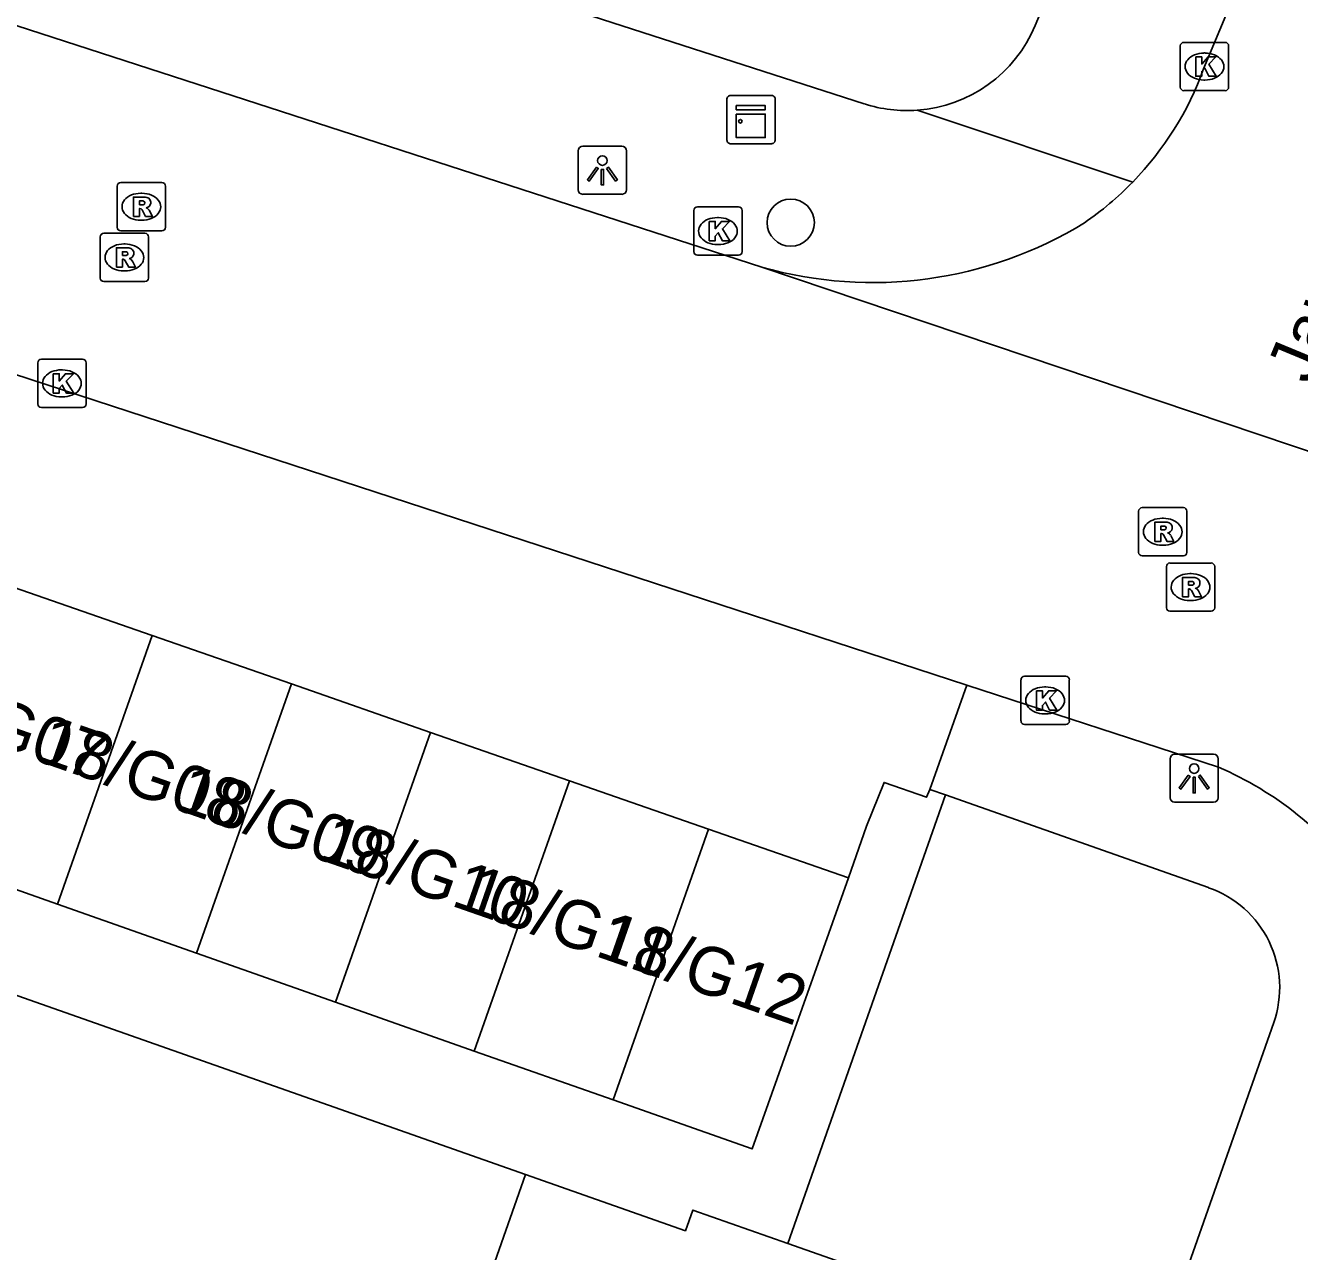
# Model space of a CAD drawing. Extents: x 163268 to 164360, y 381529 to 382285.
# Drawn here: x 163881.64 to 163908.02, y 381955.99 to 381981.39 of the extents above; entities that cross this region are included whole.
import ezdxf

# ---------------------------------------------------------------- set-up
doc = ezdxf.new("R2010")
doc.units = 0
for name, color, linetype in [('IMGEO_Boom', 7, 'Continuous'), ('IMGEO_Kast', 7, 'Continuous'), ('IMGEO_Kolk', 7, 'Continuous'), ('IMGEO_Lichtpunt', 7, 'Continuous'), ('IMGEO_Openbare_ruimte_label', 7, 'Continuous'), ('IMGEO_Pand', 7, 'Continuous'), ('IMGEO_Pand_nummerreeks', 7, 'Continuous'), ('IMGEO_Rijbaan_lokaal_open', 7, 'Continuous'), ('IMGEO_Rioolput', 7, 'Continuous'), ('IMGEO_Voetpad_open', 7, 'Continuous')]:
    doc.layers.add(name, color=color, linetype=linetype)

msp = doc.modelspace()

# ---------------------------------------------------------------- linework, layer by layer
at = {"layer": 'IMGEO_Boom'}
msp.add_circle((163897.485, 381977.305), 0.489, dxfattribs=at)
at = {"layer": 'IMGEO_Kast'}
for p, q in [((163896.163, 381979.014), (163896.163, 381979.855)), ((163896.163, 381979.855), (163896.163, 381979.014)), ((163896.238, 381979.939), (163897.079, 381979.939)), ((163897.079, 381979.939), (163896.238, 381979.939)), ((163897.163, 381979.864), (163897.163, 381979.023)), ((163897.163, 381979.023), (163897.163, 381979.864)), ((163897.088, 381978.939), (163896.247, 381978.939)), ((163896.247, 381978.939), (163897.088, 381978.939))]:
    msp.add_line(p, q, dxfattribs=at)
for points in [[(163896.358, 381979.729), (163896.958, 381979.729), (163896.958, 381979.644), (163896.358, 381979.644), (163896.358, 381979.729)], [(163896.358, 381979.554), (163896.958, 381979.554), (163896.958, 381979.065), (163896.358, 381979.065), (163896.358, 381979.554)]]:
    msp.add_lwpolyline(points, dxfattribs=at)
msp.add_circle((163896.442, 381979.403), 0.0377, dxfattribs=at)
for centre, start, end in [((163896.241, 381979.861), 92.4484, 184.2845), ((163896.241, 381979.861), 92.4484, 184.2845), ((163897.085, 381979.861), 2.4484, 94.2845), ((163897.085, 381979.861), 2.4484, 94.2845), ((163896.241, 381979.017), 182.4484, 274.2845), ((163896.241, 381979.017), 182.4484, 274.2845), ((163897.085, 381979.017), 272.4484, 4.2845), ((163897.085, 381979.017), 272.4484, 4.2845)]:
    msp.add_arc(centre, 0.0779, start, end, dxfattribs=at)
at = {"layer": 'IMGEO_Kolk'}
for p, q in [((163905.552, 381980.112), (163905.552, 381980.964)), ((163905.627, 381981.038), (163906.479, 381981.038)), ((163906.04, 381980.818), (163906.065, 381980.818)), ((163906.553, 381980.964), (163906.553, 381980.112)), ((163906.479, 381980.038), (163905.627, 381980.038)), ((163906.063, 381980.258), (163906.038, 381980.258)), ((163895.477, 381976.704), (163895.477, 381977.556)), ((163895.552, 381977.63), (163896.404, 381977.63)), ((163895.965, 381977.41), (163895.99, 381977.41)), ((163896.478, 381977.556), (163896.478, 381976.704)), ((163895.988, 381976.85), (163895.963, 381976.85)), ((163896.404, 381976.63), (163895.552, 381976.63)), ((163881.967, 381974.475), (163882.819, 381974.475)), ((163881.892, 381973.549), (163881.892, 381974.401)), ((163882.38, 381974.255), (163882.405, 381974.255)), ((163882.893, 381974.401), (163882.893, 381973.549)), ((163882.403, 381973.695), (163882.378, 381973.695)), ((163882.819, 381973.475), (163881.967, 381973.475)), ((163902.328, 381967.909), (163903.18, 381967.909)), ((163902.253, 381966.983), (163902.253, 381967.835)), ((163902.741, 381967.689), (163902.766, 381967.689)), ((163903.254, 381967.835), (163903.254, 381966.983)), ((163902.764, 381967.129), (163902.739, 381967.129)), ((163903.18, 381966.909), (163902.328, 381966.909))]:
    msp.add_line(p, q, dxfattribs=at)
for points in [[(163905.552, 381980.112), (163905.552, 381980.964)], [(163905.627, 381981.038), (163906.479, 381981.038)], [(163906.553, 381980.964), (163906.553, 381980.112)], [(163905.873, 381980.738), (163905.996, 381980.738), (163905.996, 381980.587), (163906.126, 381980.738), (163906.29, 381980.738), (163906.144, 381980.587), (163906.297, 381980.338), (163906.145, 381980.338), (163906.06, 381980.502), (163905.996, 381980.435), (163905.996, 381980.338), (163905.873, 381980.338), (163905.873, 381980.738)], [(163906.479, 381980.038), (163905.627, 381980.038)], [(163895.477, 381976.704), (163895.477, 381977.556)], [(163895.552, 381977.63), (163896.404, 381977.63)], [(163896.478, 381977.556), (163896.478, 381976.704)], [(163895.798, 381977.33), (163895.921, 381977.33), (163895.921, 381977.179), (163896.051, 381977.33), (163896.215, 381977.33), (163896.069, 381977.179), (163896.222, 381976.93), (163896.07, 381976.93), (163895.985, 381977.094), (163895.921, 381977.027), (163895.921, 381976.93), (163895.798, 381976.93), (163895.798, 381977.33)], [(163896.404, 381976.63), (163895.552, 381976.63)], [(163881.967, 381974.475), (163882.819, 381974.475)], [(163881.892, 381973.549), (163881.892, 381974.401)], [(163882.893, 381974.401), (163882.893, 381973.549)], [(163882.213, 381974.175), (163882.336, 381974.175), (163882.336, 381974.024), (163882.466, 381974.175), (163882.63, 381974.175), (163882.484, 381974.024), (163882.637, 381973.775), (163882.485, 381973.775), (163882.4, 381973.939), (163882.336, 381973.872), (163882.336, 381973.775), (163882.213, 381973.775), (163882.213, 381974.175)], [(163882.819, 381973.475), (163881.967, 381973.475)], [(163902.328, 381967.909), (163903.18, 381967.909)], [(163902.253, 381966.983), (163902.253, 381967.835)], [(163902.574, 381967.609), (163902.697, 381967.609), (163902.697, 381967.458), (163902.827, 381967.609), (163902.991, 381967.609), (163902.845, 381967.458), (163902.998, 381967.209), (163902.846, 381967.209), (163902.761, 381967.373), (163902.697, 381967.306), (163902.697, 381967.209), (163902.574, 381967.209), (163902.574, 381967.609)], [(163903.254, 381967.835), (163903.254, 381966.983)], [(163903.18, 381966.909), (163902.328, 381966.909)]]:
    msp.add_lwpolyline(points, dxfattribs=at)
for centre, start, end in [((163905.629, 381980.962), 91.552, 178.448), ((163905.629, 381980.962), 91.552, 178.448), ((163906.477, 381980.962), 1.552, 88.448), ((163906.477, 381980.962), 1.552, 88.448), ((163905.629, 381980.114), 181.552, 268.448), ((163905.629, 381980.114), 181.552, 268.448), ((163906.477, 381980.114), 271.552, 358.448), ((163906.477, 381980.114), 271.552, 358.448), ((163895.554, 381977.554), 91.552, 178.448), ((163895.554, 381977.554), 91.552, 178.448), ((163896.402, 381977.554), 1.552, 88.448), ((163896.402, 381977.554), 1.552, 88.448), ((163895.554, 381976.706), 181.552, 268.448), ((163895.554, 381976.706), 181.552, 268.448), ((163896.402, 381976.706), 271.552, 358.448), ((163896.402, 381976.706), 271.552, 358.448), ((163881.969, 381974.399), 91.552, 178.448), ((163881.969, 381974.399), 91.552, 178.448), ((163882.817, 381974.399), 1.552, 88.448), ((163882.817, 381974.399), 1.552, 88.448), ((163881.969, 381973.551), 181.552, 268.448), ((163881.969, 381973.551), 181.552, 268.448), ((163882.817, 381973.551), 271.552, 358.448), ((163882.817, 381973.551), 271.552, 358.448), ((163902.33, 381967.833), 91.552, 178.448), ((163902.33, 381967.833), 91.552, 178.448), ((163903.178, 381967.833), 1.552, 88.448), ((163903.178, 381967.833), 1.552, 88.448), ((163902.33, 381966.985), 181.552, 268.448), ((163902.33, 381966.985), 181.552, 268.448), ((163903.178, 381966.985), 271.552, 358.448), ((163903.178, 381966.985), 271.552, 358.448)]:
    msp.add_arc(centre, 0.0765, start, end, dxfattribs=at)
for centre, major_axis, ratio, start_param, end_param in [((163906.039, 381980.538), (-0.387, 0.002), 0.722429, 4.712389, 7.853982), ((163906.064, 381980.538), (-0.39, 0.002), 0.717154, 1.570796, 4.712389), ((163895.964, 381977.13), (-0.387, 0.002), 0.722429, 4.712389, 7.853982), ((163895.989, 381977.13), (-0.39, 0.002), 0.717154, 1.570796, 4.712389), ((163882.379, 381973.975), (-0.387, 0.002), 0.722429, 4.712389, 7.853982), ((163882.404, 381973.975), (-0.39, 0.002), 0.717154, 1.570796, 4.712389), ((163902.74, 381967.409), (-0.387, 0.002), 0.722429, 4.712389, 7.853982), ((163902.765, 381967.409), (-0.39, 0.002), 0.717154, 1.570796, 4.712389)]:
    msp.add_ellipse(centre, major_axis=major_axis, ratio=ratio, start_param=start_param, end_param=end_param, dxfattribs=at)
at = {"layer": 'IMGEO_Lichtpunt'}
for p, q in [((163893.086, 381978.792), (163893.086, 381977.985)), ((163893.086, 381978.792), (163893.086, 381977.985)), ((163893.988, 381978.887), (163893.18, 381978.887)), ((163893.988, 381978.887), (163893.18, 381978.887)), ((163894.082, 381977.985), (163894.082, 381978.792)), ((163894.082, 381977.985), (163894.082, 381978.792)), ((163893.18, 381977.891), (163893.988, 381977.891)), ((163893.18, 381977.891), (163893.988, 381977.891)), ((163906.242, 381966.295), (163905.434, 381966.295)), ((163906.242, 381966.295), (163905.434, 381966.295)), ((163905.34, 381966.2), (163905.34, 381965.393)), ((163905.34, 381966.2), (163905.34, 381965.393)), ((163906.336, 381965.393), (163906.336, 381966.2)), ((163906.336, 381965.393), (163906.336, 381966.2)), ((163905.434, 381965.299), (163906.242, 381965.299)), ((163905.434, 381965.299), (163906.242, 381965.299))]:
    msp.add_line(p, q, dxfattribs=at)
for points in [[(163893.46, 381978.456), (163893.499, 381978.428), (163893.311, 381978.166), (163893.273, 381978.193), (163893.46, 381978.456)], [(163893.672, 381978.428), (163893.71, 381978.455), (163893.897, 381978.193), (163893.858, 381978.165), (163893.672, 381978.428)], [(163893.562, 381978.408), (163893.609, 381978.408), (163893.609, 381978.086), (163893.562, 381978.086), (163893.562, 381978.408)], [(163905.714, 381965.864), (163905.753, 381965.836), (163905.565, 381965.574), (163905.527, 381965.601), (163905.714, 381965.864)], [(163905.816, 381965.816), (163905.863, 381965.816), (163905.863, 381965.494), (163905.816, 381965.494), (163905.816, 381965.816)], [(163905.926, 381965.836), (163905.964, 381965.863), (163906.151, 381965.601), (163906.112, 381965.573), (163905.926, 381965.836)]]:
    msp.add_lwpolyline(points, dxfattribs=at)
for centre in [(163893.585, 381978.59), (163905.839, 381965.998)]:
    msp.add_circle(centre, 0.0994, dxfattribs=at)
for centre, start, end in [((163893.18, 381978.792), 90, 180), ((163893.18, 381978.792), 90, 180), ((163893.988, 381978.792), 0, 90), ((163893.988, 381978.792), 0, 90), ((163893.18, 381977.985), 180, 270), ((163893.18, 381977.985), 180, 270), ((163893.988, 381977.985), 270, 0), ((163893.988, 381977.985), 270, 360), ((163905.434, 381966.2), 90, 180), ((163905.434, 381966.2), 90, 180), ((163906.242, 381966.2), 0, 90), ((163906.242, 381966.2), 0, 90), ((163905.434, 381965.393), 180, 270), ((163905.434, 381965.393), 180, 270), ((163906.242, 381965.393), 270, 0), ((163906.242, 381965.393), 270, 360)]:
    msp.add_arc(centre, 0.0946, start, end, dxfattribs=at)
at = {"layer": 'IMGEO_Pand'}
for points in [[(163881.384, 381969.754), (163884.264, 381968.751)], [(163884.264, 381968.751), (163882.303, 381963.188)], [(163884.264, 381968.751), (163887.144, 381967.749)], [(163885.179, 381962.174), (163887.144, 381967.749)], [(163887.144, 381967.749), (163890.024, 381966.746)], [(163888.055, 381961.161), (163890.024, 381966.746)], [(163890.024, 381966.746), (163892.903, 381965.743)], [(163892.903, 381965.743), (163890.931, 381960.147)], [(163892.903, 381965.743), (163895.783, 381964.74)], [(163893.807, 381959.134), (163895.783, 381964.74)], [(163895.783, 381964.74), (163898.682, 381963.731)], [(163879.428, 381964.202), (163882.303, 381963.188)], [(163893.807, 381959.134), (163896.683, 381958.12), (163898.682, 381963.731)], [(163882.303, 381963.188), (163885.179, 381962.174)], [(163885.179, 381962.174), (163888.055, 381961.161)], [(163888.055, 381961.161), (163890.931, 381960.147)], [(163890.931, 381960.147), (163893.807, 381959.134)], [(163891.993, 381957.589), (163890.722, 381953.975), (163889.376, 381954.449), (163888.571, 381952.16)], [(163891.993, 381957.589), (163895.304, 381956.424), (163895.455, 381956.853), (163897.424, 381956.16)], [(163898.118, 381948.809), (163898.987, 381951.28), (163898.698, 381951.381), (163900.053, 381955.236), (163897.424, 381956.16)]]:
    msp.add_lwpolyline(points, dxfattribs=at)
at = {"layer": 'IMGEO_Rijbaan_lokaal_open'}
for points in [[(163906.035, 381980.488), (163914.197, 382000), (163924.045, 382023.039), (163925.558, 382026.791)], [(163757.318, 382021.706), (163762.591, 382019.997), (163809.167, 382005.041), (163831.384, 381997.714), (163849.853, 381991.631), (163896.886, 381976.383)], [(163901.134, 381967.725), (163865.382, 381979.397)], [(163914.704, 381970.381), (163896.886, 381976.383)], [(163906.341, 381966.025), (163901.134, 381967.725)]]:
    msp.add_lwpolyline(points, dxfattribs=at)
for centre, radius, start, end in [((163899.821, 381982.752), 6.614, 315.8586, 339.9812), ((163899.771, 381982.803), 6.685, 304.5762, 315.8401), ((163899.18, 381984.464), 8.401, 254.153, 301.4653), ((163903.593, 381959.579), 7.007, 35.5378, 66.9112)]:
    msp.add_arc(centre, radius, start, end, dxfattribs=at)
at = {"layer": 'IMGEO_Rioolput'}
for p, q in [((163883.537, 381977.208), (163883.537, 381978.06)), ((163883.612, 381978.134), (163884.464, 381978.134)), ((163884.025, 381977.914), (163884.05, 381977.914)), ((163884.538, 381978.06), (163884.538, 381977.208)), ((163884.464, 381977.134), (163883.612, 381977.134)), ((163884.048, 381977.354), (163884.023, 381977.354)), ((163883.186, 381976.157), (163883.186, 381977.009)), ((163883.261, 381977.083), (163884.113, 381977.083)), ((163883.674, 381976.863), (163883.699, 381976.863)), ((163884.187, 381977.009), (163884.187, 381976.157)), ((163884.113, 381976.083), (163883.261, 381976.083)), ((163883.697, 381976.303), (163883.672, 381976.303)), ((163904.688, 381970.476), (163904.688, 381971.328)), ((163904.763, 381971.402), (163905.615, 381971.402)), ((163905.689, 381971.328), (163905.689, 381970.476)), ((163905.176, 381971.182), (163905.201, 381971.182)), ((163905.199, 381970.622), (163905.174, 381970.622)), ((163905.615, 381970.402), (163904.763, 381970.402)), ((163905.338, 381970.255), (163906.19, 381970.255)), ((163905.263, 381969.329), (163905.263, 381970.181)), ((163905.751, 381970.035), (163905.776, 381970.035)), ((163906.264, 381970.181), (163906.264, 381969.329)), ((163905.774, 381969.475), (163905.749, 381969.475)), ((163906.19, 381969.255), (163905.338, 381969.255))]:
    msp.add_line(p, q, dxfattribs=at)
for points in [[(163883.537, 381977.208), (163883.537, 381978.06)], [(163883.612, 381978.134), (163884.464, 381978.134)], [(163884.538, 381978.06), (163884.538, 381977.208)], [(163884.126, 381977.832), (163883.874, 381977.834), (163883.874, 381977.434)], [(163884.052, 381977.753), (163883.998, 381977.753), (163883.998, 381977.672)], [(163883.998, 381977.672), (163884.05, 381977.672)], [(163883.874, 381977.434), (163883.998, 381977.434), (163883.998, 381977.596), (163884.009, 381977.596)], [(163884.056, 381977.567), (163884.127, 381977.434), (163884.267, 381977.434), (163884.202, 381977.56)], [(163884.464, 381977.134), (163883.612, 381977.134)], [(163883.186, 381976.157), (163883.186, 381977.009)], [(163883.261, 381977.083), (163884.113, 381977.083)], [(163884.187, 381977.009), (163884.187, 381976.157)], [(163883.775, 381976.781), (163883.523, 381976.783), (163883.523, 381976.383)], [(163883.701, 381976.702), (163883.647, 381976.702), (163883.647, 381976.621)], [(163883.647, 381976.621), (163883.699, 381976.621)], [(163883.523, 381976.383), (163883.647, 381976.383), (163883.647, 381976.545), (163883.658, 381976.545)], [(163883.705, 381976.516), (163883.776, 381976.383), (163883.916, 381976.383), (163883.851, 381976.509)], [(163884.113, 381976.083), (163883.261, 381976.083)], [(163904.688, 381970.476), (163904.688, 381971.328)], [(163904.763, 381971.402), (163905.615, 381971.402)], [(163905.689, 381971.328), (163905.689, 381970.476)], [(163905.277, 381971.1), (163905.025, 381971.102), (163905.025, 381970.702)], [(163905.025, 381970.702), (163905.149, 381970.702), (163905.149, 381970.864), (163905.16, 381970.864)], [(163905.203, 381971.021), (163905.149, 381971.021), (163905.149, 381970.94)], [(163905.149, 381970.94), (163905.201, 381970.94)], [(163905.207, 381970.835), (163905.278, 381970.702), (163905.418, 381970.702), (163905.353, 381970.828)], [(163905.615, 381970.402), (163904.763, 381970.402)], [(163905.338, 381970.255), (163906.19, 381970.255)], [(163905.263, 381969.329), (163905.263, 381970.181)], [(163906.264, 381970.181), (163906.264, 381969.329)], [(163905.852, 381969.953), (163905.6, 381969.955), (163905.6, 381969.555)], [(163905.6, 381969.555), (163905.724, 381969.555), (163905.724, 381969.717), (163905.735, 381969.717)], [(163905.778, 381969.874), (163905.724, 381969.874), (163905.724, 381969.793)], [(163905.724, 381969.793), (163905.776, 381969.793)], [(163905.782, 381969.688), (163905.853, 381969.555), (163905.993, 381969.555), (163905.928, 381969.681)], [(163906.19, 381969.255), (163905.338, 381969.255)]]:
    msp.add_lwpolyline(points, dxfattribs=at)
for centre, radius, start, end in [((163883.614, 381978.058), 0.0765, 91.552, 178.448), ((163883.614, 381978.058), 0.0765, 91.552, 178.448), ((163884.462, 381978.058), 0.0765, 1.552, 88.448), ((163884.462, 381978.058), 0.0765, 1.552, 88.448), ((163884.034, 381977.861), 0.19, 274.7715, 282.9687), ((163884.058, 381977.657), 0.0964, 77.0061, 93.1865), ((163884.072, 381977.714), 0.0378, 276.6634, 79.6772), ((163884.125, 381977.722), 0.109, 350.3612, 89.416), ((163884.123, 381977.722), 0.112, 277.5842, 350.9817), ((163884.008, 381977.543), 0.0533, 26.0293, 88.6989), ((163884.107, 381977.507), 0.108, 29.5134, 73.7905), ((163883.614, 381977.21), 0.0765, 181.552, 268.448), ((163883.614, 381977.21), 0.0765, 181.552, 268.448), ((163884.462, 381977.21), 0.0765, 271.552, 358.448), ((163884.462, 381977.21), 0.0765, 271.552, 358.448), ((163883.263, 381977.007), 0.0765, 91.552, 178.448), ((163883.263, 381977.007), 0.0765, 91.552, 178.448), ((163884.111, 381977.007), 0.0765, 1.552, 88.448), ((163884.111, 381977.007), 0.0765, 1.552, 88.448), ((163883.683, 381976.81), 0.19, 274.7715, 282.9687), ((163883.707, 381976.606), 0.0964, 77.0061, 93.1865), ((163883.721, 381976.663), 0.0378, 276.6634, 79.6772), ((163883.774, 381976.671), 0.109, 350.3612, 89.416), ((163883.772, 381976.671), 0.112, 277.5842, 350.9817), ((163883.657, 381976.492), 0.0533, 26.0293, 88.6989), ((163883.756, 381976.456), 0.108, 29.5134, 73.7905), ((163883.263, 381976.159), 0.0765, 181.552, 268.448), ((163883.263, 381976.159), 0.0765, 181.552, 268.448), ((163884.111, 381976.159), 0.0765, 271.552, 358.448), ((163884.111, 381976.159), 0.0765, 271.552, 358.448), ((163904.765, 381971.326), 0.0765, 91.552, 178.448), ((163904.765, 381971.326), 0.0765, 91.552, 178.448), ((163905.613, 381971.326), 0.0765, 1.552, 88.448), ((163905.613, 381971.326), 0.0765, 1.552, 88.448), ((163905.276, 381970.99), 0.109, 350.3612, 89.416), ((163905.159, 381970.811), 0.0533, 26.0293, 88.6989), ((163905.185, 381971.129), 0.19, 274.7715, 282.9687), ((163905.209, 381970.925), 0.0964, 77.0061, 93.1865), ((163905.223, 381970.982), 0.0378, 276.6634, 79.6772), ((163905.274, 381970.99), 0.112, 277.5842, 350.9817), ((163905.258, 381970.775), 0.108, 29.5134, 73.7905), ((163904.765, 381970.478), 0.0765, 181.552, 268.448), ((163904.765, 381970.478), 0.0765, 181.552, 268.448), ((163905.34, 381970.179), 0.0765, 91.552, 178.448), ((163905.34, 381970.179), 0.0765, 91.552, 178.448), ((163905.613, 381970.478), 0.0765, 271.552, 358.448), ((163905.613, 381970.478), 0.0765, 271.552, 358.448), ((163906.188, 381970.179), 0.0765, 1.552, 88.448), ((163906.188, 381970.179), 0.0765, 1.552, 88.448), ((163905.734, 381969.664), 0.0533, 26.0293, 88.6989), ((163905.76, 381969.982), 0.19, 274.7715, 282.9687), ((163905.784, 381969.778), 0.0964, 77.0061, 93.1865), ((163905.798, 381969.835), 0.0378, 276.6634, 79.6772), ((163905.851, 381969.843), 0.109, 350.3612, 89.416), ((163905.849, 381969.843), 0.112, 277.5842, 350.9817), ((163905.833, 381969.628), 0.108, 29.5134, 73.7905), ((163905.34, 381969.331), 0.0765, 181.552, 268.448), ((163905.34, 381969.331), 0.0765, 181.552, 268.448), ((163906.188, 381969.331), 0.0765, 271.552, 358.448), ((163906.188, 381969.331), 0.0765, 271.552, 358.448)]:
    msp.add_arc(centre, radius, start, end, dxfattribs=at)
for centre, major_axis, ratio, start_param, end_param in [((163884.024, 381977.634), (-0.387, 0.002), 0.722429, 4.712389, 7.853982), ((163884.049, 381977.634), (-0.39, 0.002), 0.717154, 1.570796, 4.712389), ((163883.673, 381976.583), (-0.387, 0.002), 0.722429, 4.712389, 7.853982), ((163883.698, 381976.583), (-0.39, 0.002), 0.717154, 1.570796, 4.712389), ((163905.175, 381970.902), (-0.387, 0.002), 0.722429, 4.712389, 7.853982), ((163905.2, 381970.902), (-0.39, 0.002), 0.717154, 1.570796, 4.712389), ((163905.75, 381969.755), (-0.387, 0.002), 0.722429, 4.712389, 7.853982), ((163905.775, 381969.755), (-0.39, 0.002), 0.717154, 1.570796, 4.712389)]:
    msp.add_ellipse(centre, major_axis=major_axis, ratio=ratio, start_param=start_param, end_param=end_param, dxfattribs=at)
at = {"layer": 'IMGEO_Voetpad_open'}
for points in [[(163921.794, 382027.056), (163910.392, 382000), (163902.548, 381981.388)], [(163899.009, 381979.765), (163876.662, 381986.975)], [(163904.567, 381978.146), (163900.106, 381979.633)], [(163901.134, 381967.725), (163900.368, 381965.565)], [(163898.682, 381963.731), (163899.056, 381964.805), (163899.419, 381965.709), (163900.297, 381965.405), (163900.368, 381965.565)], [(163900.368, 381965.565), (163900.692, 381965.451)], [(163897.424, 381956.16), (163900.692, 381965.451)], [(163900.692, 381965.451), (163906.138, 381963.531)], [(163878.299, 381958.54), (163879.494, 381961.987), (163891.993, 381957.589)], [(163907.487, 381960.738), (163890.945, 381913.685)]]:
    msp.add_lwpolyline(points, dxfattribs=at)
for centre, radius, start, end in [((163899.897, 381982.501), 2.876, 274.1766, 337.231), ((163899.896, 381982.51), 2.885, 252.0973, 274.1801), ((163905.419, 381961.461), 2.191, 340.7175, 70.843)]:
    msp.add_arc(centre, radius, start, end, dxfattribs=at)

# ---------------------------------------------------------------- texts
at = {"layer": 'IMGEO_Openbare_ruimte_label'}
msp.add_text('Jan Sluytersweg', height=1, rotation=67.4859, dxfattribs=at).set_placement((163908.24, 381973.927))
at = {"layer": 'IMGEO_Pand_nummerreeks'}
for s, p in [('18/G07', (163878.952, 381967.176)), ('18/G08', (163881.837, 381966.169)), ('18/G09', (163884.713, 381965.164)), ('18/G10', (163887.687, 381964.124)), ('18/G11', (163890.67, 381963.082)), ('18/G12', (163893.442, 381962.114))]:
    msp.add_text(s, height=1, rotation=340.7407, dxfattribs=at).set_placement(p)

doc.saveas('drawing.dxf')
